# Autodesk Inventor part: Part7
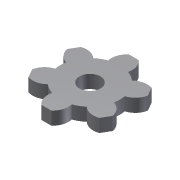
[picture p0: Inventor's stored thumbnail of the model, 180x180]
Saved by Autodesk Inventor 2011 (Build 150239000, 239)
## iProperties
Created: 2002-01
Part Number: Part7
Document SubType Name: Modeling
Designer: ***
Density: 1 g/cm^3
Control State: 0
Master: False
Checked Out: False
Shininess: 77.0
Angle Display Precision: 2
Document Length Units: 11269
Document Angle Units: 11279
Document Time Units: 11290
Document Mass Units: 11283
Document Length Units Precision: 3
Document Angle Units Precision: 2
Density: 0.0
Volumn: 0.0
Area: 0.0
PropertySet Name: Model Information
Author: ***
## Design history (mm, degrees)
sketch "Sketch1"
  geometry: L1 (-3.771, 33.333)-(3.771, 33.333); L2 (-30.753, 13.401)-(-26.982, 19.933); L3 (-30.753, -13.401)-(-26.982, -19.933); L4 (-3.771, -33.333)-(3.771, -33.333); L5 (30.753, 13.401)-(26.982, 19.933); L6 (30.753, -13.401)-(26.982, -19.933); C1 r 8 at (0, 0); A1 r 11.863 centre (3.952, 24.328) between (-3.771, 33.333) and (-7.559, 21.457); A2 r 11.863 centre (-3.952, 24.328) between (7.559, 21.457) and (3.771, 33.333); A3 r 11.863 centre (-19.093, 15.587) between (-30.753, 13.401) and (-22.362, 4.182); A4 r 11.863 centre (-23.045, 8.742) between (-14.803, 17.275) and (-26.982, 19.933); A5 r 22.749 centre (0, 0) between (-7.559, 21.457) and (-14.803, 17.275); A6 r 11.863 centre (-23.045, -8.742) between (-26.982, -19.933) and (-14.803, -17.275); A7 r 11.863 centre (-19.093, -15.587) between (-22.362, -4.182) and (-30.753, -13.401); A8 r 11.863 centre (3.952, -24.328) between (-7.559, -21.457) and (-3.771, -33.333); A9 r 11.863 centre (-3.952, -24.328) between (3.771, -33.333) and (7.559, -21.457); A10 r 11.863 centre (23.045, 8.742) between (26.982, 19.933) and (14.803, 17.275); A11 r 11.863 centre (19.093, 15.587) between (22.362, 4.182) and (30.753, 13.401); A12 r 11.863 centre (19.093, -15.587) between (30.753, -13.401) and (22.362, -4.182); A13 r 11.863 centre (23.045, -8.742) between (14.803, -17.275) and (26.982, -19.933); A14 r 22.749 centre (0, 0) between (-22.362, 4.182) and (-22.362, -4.182); A15 r 22.749 centre (0, 0) between (-14.803, -17.275) and (-7.559, -21.457); A16 r 22.749 centre (0, 0) between (7.559, -21.457) and (14.803, -17.275); A17 r 22.749 centre (0, 0) between (22.362, -4.182) and (22.362, 4.182); A18 r 22.749 centre (0, 0) between (14.803, 17.275) and (7.559, 21.457)
  constraints: 36 point on circle, 19 centre point, 12 end point, 1 coincident
  dimensions: "d2" = 16 diameter of C1
extrude "Extrusion1" new body sketch "Sketch1" distance "d0" = 10; taper "d1" = 0 deg
body "Solid1"
